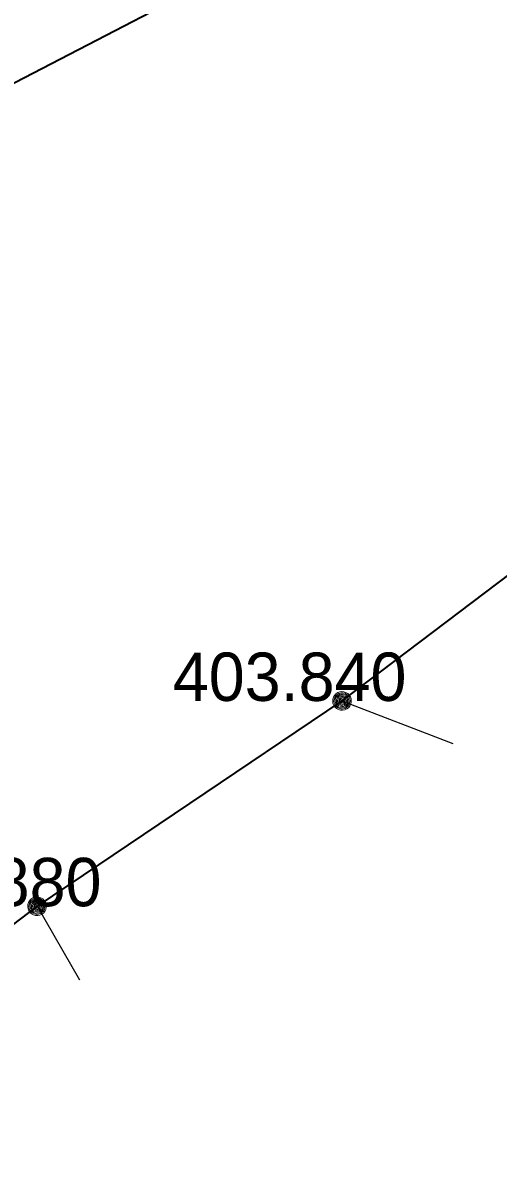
# Model space of a CAD drawing. Extents: x -873619 to -867639, y -1015082 to -1012326.
# Drawn here: x -867967.9 to -867956.09, y -1012720.88 to -1012692.71 of the extents above; entities that cross this region are included whole.
import ezdxf

# ---------------------------------------------------------------- set-up
doc = ezdxf.new("R2010")
doc.units = 0
doc.header["$LTSCALE"] = 0.44
for name, color, linetype, lineweight in [('1', 7, 'Continuous', 13), ('21', 7, 'Continuous', 35), ('3', 7, 'Continuous', 25)]:
    doc.layers.add(name, color=color, linetype=linetype, lineweight=lineweight)

msp = doc.modelspace()

# ---------------------------------------------------------------- linework, layer by layer
at = {"layer": '1', "lineweight": 35}
msp.add_lwpolyline([(-867928.158, -1012682.175), (-867928.532, -1012682.575), (-867928.834, -1012682.846), (-867929.235, -1012683.248), (-867941.259, -1012695.377), (-867959.972, -1012709.533), (-867967.543, -1012714.627), (-867970.064, -1012716.534), (-867974.611, -1012725.697)], dxfattribs=at)
at = {"layer": '1'}
for points in [[(-867959.74, -1012709.533), (-867959.747, -1012709.481), (-867959.764, -1012709.431), (-867959.793, -1012709.387), (-867959.83, -1012709.35), (-867959.875, -1012709.323), (-867959.924, -1012709.306), (-867959.978, -1012709.302), (-867960.029, -1012709.309), (-867960.078, -1012709.328), (-867960.122, -1012709.357), (-867960.157, -1012709.396), (-867960.184, -1012709.441), (-867960.2, -1012709.492), (-867960.203, -1012709.544), (-867960.195, -1012709.596), (-867960.174, -1012709.645), (-867960.144, -1012709.688), (-867960.105, -1012709.722), (-867960.059, -1012709.748), (-867960.007, -1012709.762), (-867959.955, -1012709.764), (-867959.904, -1012709.754), (-867959.855, -1012709.733), (-867959.813, -1012709.702), (-867959.779, -1012709.661), (-867959.755, -1012709.615), (-867959.742, -1012709.564)], [(-867959.771, -1012709.533), (-867959.777, -1012709.484), (-867959.794, -1012709.438), (-867959.821, -1012709.398), (-867959.858, -1012709.366), (-867959.902, -1012709.344), (-867959.951, -1012709.333), (-867960, -1012709.333), (-867960.046, -1012709.346), (-867960.09, -1012709.37), (-867960.125, -1012709.403), (-867960.152, -1012709.444), (-867960.169, -1012709.491), (-867960.173, -1012709.54), (-867960.166, -1012709.588), (-867960.147, -1012709.633), (-867960.117, -1012709.673), (-867960.078, -1012709.704), (-867960.034, -1012709.724), (-867959.987, -1012709.734), (-867959.938, -1012709.732), (-867959.891, -1012709.717), (-867959.848, -1012709.692), (-867959.813, -1012709.658), (-867959.788, -1012709.616), (-867959.774, -1012709.569)], [(-867959.801, -1012709.533), (-867959.806, -1012709.488), (-867959.823, -1012709.446), (-867959.852, -1012709.411), (-867959.887, -1012709.384), (-867959.929, -1012709.367), (-867959.975, -1012709.362), (-867960.019, -1012709.368), (-867960.061, -1012709.387), (-867960.095, -1012709.415), (-867960.122, -1012709.452), (-867960.139, -1012709.494), (-867960.142, -1012709.539), (-867960.136, -1012709.584), (-867960.117, -1012709.625), (-867960.088, -1012709.659), (-867960.051, -1012709.685), (-867960.007, -1012709.701), (-867959.963, -1012709.704), (-867959.918, -1012709.696), (-867959.877, -1012709.676), (-867959.843, -1012709.647), (-867959.818, -1012709.609), (-867959.804, -1012709.566)], [(-867959.831, -1012709.533), (-867959.835, -1012709.492), (-867959.853, -1012709.455), (-867959.88, -1012709.424), (-867959.916, -1012709.403), (-867959.956, -1012709.392), (-867959.997, -1012709.394), (-867960.036, -1012709.407), (-867960.07, -1012709.431), (-867960.095, -1012709.463), (-867960.11, -1012709.501), (-867960.112, -1012709.542), (-867960.105, -1012709.582), (-867960.085, -1012709.618), (-867960.056, -1012709.647), (-867960.019, -1012709.666), (-867959.978, -1012709.674), (-867959.938, -1012709.67), (-867959.899, -1012709.655), (-867959.867, -1012709.629), (-867959.845, -1012709.595), (-867959.831, -1012709.556)], [(-867959.86, -1012709.533), (-867959.865, -1012709.497), (-867959.884, -1012709.465), (-867959.909, -1012709.44), (-867959.943, -1012709.425), (-867959.98, -1012709.422), (-867960.014, -1012709.43), (-867960.046, -1012709.45), (-867960.068, -1012709.478), (-867960.081, -1012709.512), (-867960.081, -1012709.549), (-867960.071, -1012709.584), (-867960.049, -1012709.613), (-867960.019, -1012709.634), (-867959.985, -1012709.644), (-867959.948, -1012709.642), (-867959.914, -1012709.628), (-867959.887, -1012709.605), (-867959.867, -1012709.573), (-867959.86, -1012709.538)], [(-867959.891, -1012709.533), (-867959.896, -1012709.502), (-867959.913, -1012709.476), (-867959.938, -1012709.459), (-867959.968, -1012709.452), (-867960, -1012709.456), (-867960.027, -1012709.473), (-867960.044, -1012709.497), (-867960.053, -1012709.528), (-867960.049, -1012709.558), (-867960.034, -1012709.586), (-867960.009, -1012709.605), (-867959.98, -1012709.614), (-867959.948, -1012709.611), (-867959.921, -1012709.597), (-867959.901, -1012709.573), (-867959.891, -1012709.544)], [(-867959.921, -1012709.533), (-867959.926, -1012709.509), (-867959.943, -1012709.491), (-867959.965, -1012709.482), (-867959.99, -1012709.485), (-867960.011, -1012709.499), (-867960.022, -1012709.521), (-867960.022, -1012709.546), (-867960.009, -1012709.567), (-867959.99, -1012709.581), (-867959.965, -1012709.584), (-867959.941, -1012709.575), (-867959.926, -1012709.557)], [(-867959.951, -1012709.533), (-867959.956, -1012709.518), (-867959.97, -1012709.512), (-867959.985, -1012709.516), (-867959.992, -1012709.53), (-867959.989, -1012709.545), (-867959.975, -1012709.554), (-867959.96, -1012709.551), (-867959.951, -1012709.539)], [(-867967.311, -1012714.627), (-867967.318, -1012714.575), (-867967.335, -1012714.525), (-867967.364, -1012714.481), (-867967.401, -1012714.444), (-867967.446, -1012714.417), (-867967.495, -1012714.4), (-867967.549, -1012714.396), (-867967.6, -1012714.403), (-867967.649, -1012714.422), (-867967.693, -1012714.451), (-867967.728, -1012714.49), (-867967.755, -1012714.535), (-867967.771, -1012714.586), (-867967.774, -1012714.638), (-867967.766, -1012714.69), (-867967.745, -1012714.739), (-867967.715, -1012714.782), (-867967.676, -1012714.816), (-867967.63, -1012714.842), (-867967.578, -1012714.856), (-867967.526, -1012714.858), (-867967.475, -1012714.848), (-867967.426, -1012714.827), (-867967.384, -1012714.796), (-867967.35, -1012714.755), (-867967.326, -1012714.709), (-867967.313, -1012714.658)], [(-867967.342, -1012714.627), (-867967.348, -1012714.578), (-867967.365, -1012714.532), (-867967.392, -1012714.492), (-867967.429, -1012714.46), (-867967.473, -1012714.438), (-867967.522, -1012714.427), (-867967.571, -1012714.427), (-867967.617, -1012714.44), (-867967.661, -1012714.464), (-867967.696, -1012714.497), (-867967.723, -1012714.538), (-867967.74, -1012714.585), (-867967.744, -1012714.634), (-867967.737, -1012714.682), (-867967.718, -1012714.727), (-867967.688, -1012714.767), (-867967.649, -1012714.798), (-867967.605, -1012714.818), (-867967.558, -1012714.828), (-867967.509, -1012714.826), (-867967.462, -1012714.811), (-867967.419, -1012714.786), (-867967.384, -1012714.752), (-867967.358, -1012714.71), (-867967.345, -1012714.663)], [(-867967.372, -1012714.627), (-867967.377, -1012714.582), (-867967.394, -1012714.54), (-867967.423, -1012714.505), (-867967.458, -1012714.478), (-867967.5, -1012714.461), (-867967.546, -1012714.456), (-867967.59, -1012714.462), (-867967.632, -1012714.481), (-867967.666, -1012714.509), (-867967.693, -1012714.546), (-867967.71, -1012714.588), (-867967.713, -1012714.633), (-867967.706, -1012714.678), (-867967.688, -1012714.719), (-867967.659, -1012714.753), (-867967.622, -1012714.779), (-867967.578, -1012714.795), (-867967.534, -1012714.798), (-867967.489, -1012714.79), (-867967.448, -1012714.77), (-867967.414, -1012714.741), (-867967.389, -1012714.703), (-867967.375, -1012714.66)], [(-867967.402, -1012714.627), (-867967.406, -1012714.586), (-867967.424, -1012714.549), (-867967.451, -1012714.518), (-867967.487, -1012714.497), (-867967.527, -1012714.486), (-867967.568, -1012714.488), (-867967.607, -1012714.501), (-867967.641, -1012714.525), (-867967.666, -1012714.557), (-867967.681, -1012714.595), (-867967.683, -1012714.636), (-867967.676, -1012714.676), (-867967.656, -1012714.712), (-867967.627, -1012714.741), (-867967.59, -1012714.76), (-867967.549, -1012714.768), (-867967.509, -1012714.764), (-867967.47, -1012714.749), (-867967.438, -1012714.723), (-867967.416, -1012714.689), (-867967.402, -1012714.65)], [(-867967.431, -1012714.627), (-867967.436, -1012714.591), (-867967.455, -1012714.559), (-867967.48, -1012714.534), (-867967.514, -1012714.519), (-867967.551, -1012714.516), (-867967.585, -1012714.524), (-867967.617, -1012714.544), (-867967.639, -1012714.572), (-867967.652, -1012714.606), (-867967.652, -1012714.643), (-867967.642, -1012714.678), (-867967.62, -1012714.707), (-867967.59, -1012714.728), (-867967.556, -1012714.738), (-867967.519, -1012714.736), (-867967.485, -1012714.722), (-867967.458, -1012714.699), (-867967.438, -1012714.667), (-867967.431, -1012714.632)], [(-867967.462, -1012714.627), (-867967.467, -1012714.596), (-867967.483, -1012714.57), (-867967.509, -1012714.553), (-867967.539, -1012714.546), (-867967.571, -1012714.55), (-867967.598, -1012714.567), (-867967.615, -1012714.591), (-867967.624, -1012714.622), (-867967.62, -1012714.652), (-867967.605, -1012714.68), (-867967.58, -1012714.699), (-867967.551, -1012714.708), (-867967.519, -1012714.705), (-867967.492, -1012714.691), (-867967.472, -1012714.667), (-867967.462, -1012714.638)], [(-867967.492, -1012714.627), (-867967.497, -1012714.603), (-867967.514, -1012714.585), (-867967.536, -1012714.576), (-867967.561, -1012714.579), (-867967.581, -1012714.593), (-867967.593, -1012714.615), (-867967.593, -1012714.64), (-867967.58, -1012714.661), (-867967.561, -1012714.675), (-867967.536, -1012714.678), (-867967.512, -1012714.669), (-867967.497, -1012714.651)], [(-867967.522, -1012714.627), (-867967.527, -1012714.612), (-867967.541, -1012714.606), (-867967.556, -1012714.61), (-867967.563, -1012714.624), (-867967.559, -1012714.639), (-867967.546, -1012714.648), (-867967.531, -1012714.645), (-867967.522, -1012714.633)]]:
    msp.add_lwpolyline(points, close=True, dxfattribs=at)
at = {"layer": '21'}
msp.add_lwpolyline([(-867964.04, -1012692.09), (-867981.81, -1012701.3), (-867981.801, -1012701.313)], dxfattribs=at)
at = {"layer": '3'}
for p, q in [((-867959.972, -1012709.533), (-867957.222, -1012710.59)), ((-867967.543, -1012714.627), (-867966.489, -1012716.451))]:
    msp.add_line(p, q, dxfattribs=at)

# ---------------------------------------------------------------- texts
at = {"layer": '1'}
for s, p in [('403.840 ', (-867964.172, -1012709.533)), ('403.880 ', (-867971.743, -1012714.627))]:
    msp.add_text(s, height=1.2, dxfattribs=at).set_placement(p)

doc.saveas('drawing.dxf')
